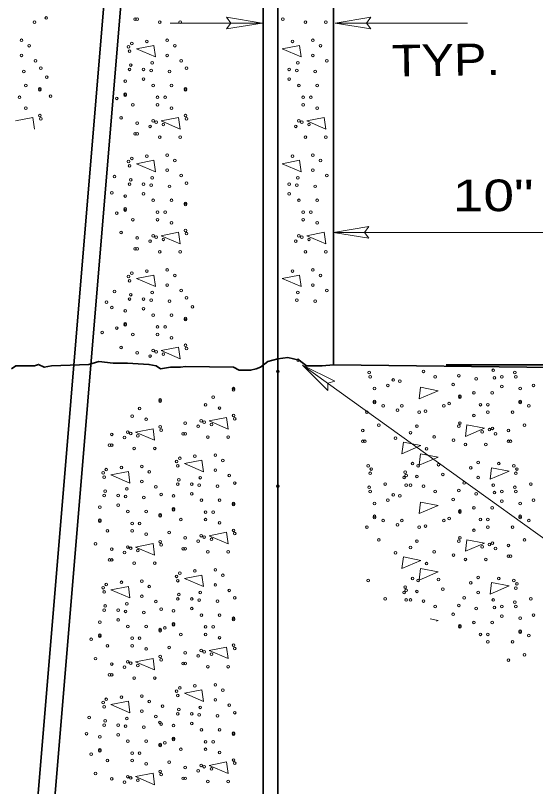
# Model space of a CAD drawing. Extents: x -16.43 to -9.36, y -8.57 to 1.26.
# Drawn here: x -13.889 to -12.904, y -2.302 to -0.843 of the extents above; entities that cross this region are included whole.
import ezdxf
from ezdxf.enums import TextEntityAlignment as Align

# ---------------------------------------------------------------- set-up
doc = ezdxf.new("R2010")
doc.units = 0
doc.header["$LTSCALE"] = 0.024
for name, color, linetype, lineweight in [('1', 7, 'Continuous', 35), ('10', 7, 'Continuous', 13), ('12', 7, 'Continuous', 53), ('6', 7, 'Continuous', 13)]:
    doc.layers.add(name, color=color, linetype=linetype, lineweight=lineweight)

msp = doc.modelspace()

# ---------------------------------------------------------------- linework, layer by layer
at = {"layer": '1'}
for p, q in [((-13.28633, 0.49133), (-13.28633, -1.504)), ((-13.392, 0.00867), (-13.392, -2.83033)), ((-13.66625, -0.552), (-13.85583, -2.82733)), ((-13.69975, -0.56375), (-13.88817, -2.82583)), ((-11.35133, -1.526), (-13.28633, -1.504)), ((-13.07283, -1.504), (-12.68283, -1.504))]:
    msp.add_line(p, q, dxfattribs=at)
for points in [[(-13.41917, 0.01217), (-13.41917, -2.83033), (-13.392, -2.83033)], [(-13.89617, -1.5115), (-13.888, -1.506), (-13.8745, -1.506), (-13.86083, -1.506), (-13.85267, -1.506), (-13.84467, -1.50333), (-13.83383, -1.50867), (-13.82017, -1.506), (-13.74967, -1.50333), (-13.73067, -1.49783), (-13.70367, -1.50067), (-13.6765, -1.50067), (-13.63583, -1.50333), (-13.62233, -1.506), (-13.61417, -1.5115), (-13.59517, -1.50867), (-13.57617, -1.50867), (-13.56633, -1.507)], [(-13.28633, -1.504), (-13.30767, -1.506), (-13.3375, -1.506), (-13.35117, -1.49517), (-13.37283, -1.48983), (-13.39183, -1.4925), (-13.41067, -1.49783), (-13.42433, -1.50867), (-13.4325, -1.5115), (-13.44333, -1.51417), (-13.465, -1.51417), (-13.47583, -1.50867), (-13.56633, -1.507)]]:
    msp.add_lwpolyline(points, dxfattribs=at)
msp.add_arc((-14.44102, -0.51249), 0.6001, 325.00798, 355.23636, dxfattribs=at)
at = {"layer": '10'}
for p, q in [((-13.48883, -0.84583), (-13.42167, -0.857)), ((-13.48883, -0.84583), (-13.4805, -0.857)), ((-13.21567, -0.84583), (-13.28283, -0.857)), ((-13.21567, -0.84583), (-13.224, -0.857)), ((-13.59533, -0.857), (-13.42167, -0.857)), ((-13.48883, -0.86817), (-13.42167, -0.857)), ((-13.48883, -0.86817), (-13.4805, -0.857)), ((-13.03283, -0.857), (-13.28283, -0.857)), ((-13.21567, -0.86817), (-13.28283, -0.857)), ((-13.21567, -0.86817), (-13.224, -0.857)), ((-13.21917, -1.24217), (-13.28633, -1.25333)), ((-13.21917, -1.2645), (-13.28633, -1.25333)), ((-13.21917, -1.24217), (-13.2275, -1.25333)), ((-13.21917, -1.2645), (-13.2275, -1.25333)), ((-13.297, -1.55283), (-13.345, -1.5045)), ((-13.284, -1.53467), (-13.345, -1.5045)), ((-13.284, -1.53467), (-13.29733, -1.53883)), ((-13.297, -1.55283), (-13.29733, -1.53883))]:
    msp.add_line(p, q, dxfattribs=at)
for points in [[(-13.28633, -1.25333), (-12.69033, -1.25333), (-11.3495, -1.25333)], [(-13.345, -1.5045), (-12.57717, -2.05633), (-12.43733, -2.05633)]]:
    msp.add_lwpolyline(points, dxfattribs=at)
at = {"layer": '6'}
for p, q in [((-13.08817, -1.98767), (-13.103, -1.98467)), ((-13.09117, -1.989), (-13.08817, -1.98767))]:
    msp.add_line(p, q, dxfattribs=at)
for points in [[(-13.6595, -0.906), (-13.6265, -0.8995), (-13.6235, -0.92133)], [(-13.38367, -0.906), (-13.35067, -0.8995), (-13.34783, -0.92133)], [(-13.61267, -1.04233), (-13.57967, -1.03583), (-13.57683, -1.05767)], [(-13.337, -1.04233), (-13.30383, -1.03583), (-13.301, -1.05767)], [(-13.6595, -1.12333), (-13.6265, -1.11683), (-13.6235, -1.13867)], [(-13.38367, -1.12333), (-13.35067, -1.11683), (-13.34783, -1.13867)], [(-13.61267, -1.25967), (-13.57967, -1.25317), (-13.57683, -1.27517)], [(-13.337, -1.25967), (-13.30383, -1.25317), (-13.301, -1.27517)], [(-13.6595, -1.34067), (-13.6265, -1.33417), (-13.6235, -1.356)], [(-13.38367, -1.34067), (-13.35067, -1.33417), (-13.34783, -1.356)], [(-13.61267, -1.477), (-13.57967, -1.4705), (-13.57683, -1.4925)], [(-13.08817, -1.553), (-13.12133, -1.5465), (-13.12417, -1.56833)], [(-13.52167, -1.61), (-13.48867, -1.60367), (-13.48567, -1.6255)], [(-13.00067, -1.62417), (-13.03367, -1.61767), (-13.0365, -1.63967)], [(-13.661, -1.6315), (-13.62783, -1.625), (-13.625, -1.64683)], [(-13.12067, -1.65683), (-13.15383, -1.65033), (-13.15667, -1.67217)], [(-13.08817, -1.67867), (-13.12133, -1.67217), (-13.12417, -1.694)], [(-13.5685, -1.691), (-13.53533, -1.6845), (-13.5325, -1.7065)], [(-13.70783, -1.7125), (-13.67467, -1.706), (-13.67183, -1.72783)], [(-12.95383, -1.70517), (-12.98683, -1.69867), (-12.98983, -1.7205)], [(-13.08817, -1.77033), (-13.12133, -1.76383), (-13.12417, -1.78567)], [(-13.52167, -1.8275), (-13.48867, -1.821), (-13.48567, -1.84283)], [(-13.00067, -1.8415), (-13.03367, -1.835), (-13.0365, -1.857)], [(-13.661, -1.84883), (-13.62783, -1.84233), (-13.625, -1.86417)], [(-13.12067, -1.87417), (-13.15383, -1.86767), (-13.15667, -1.8895)], [(-13.08817, -1.896), (-13.12133, -1.8895), (-13.12417, -1.9115)], [(-13.5685, -1.90833), (-13.53533, -1.90183), (-13.5325, -1.92383)], [(-13.70783, -1.92983), (-13.67467, -1.92333), (-13.67183, -1.94517)], [(-12.95383, -1.9225), (-12.98683, -1.916), (-12.98983, -1.938)], [(-13.52167, -2.04483), (-13.48867, -2.03833), (-13.48567, -2.06017)], [(-13.661, -2.06617), (-13.62783, -2.05967), (-13.625, -2.0815)], [(-13.5685, -2.12567), (-13.53533, -2.11933), (-13.5325, -2.14117)], [(-13.70783, -2.14717), (-13.67467, -2.14067), (-13.67183, -2.1625)], [(-13.52167, -2.26217), (-13.48867, -2.25567), (-13.48567, -2.2775)], [(-13.661, -2.2835), (-13.62783, -2.277), (-13.625, -2.299)]]:
    msp.add_lwpolyline(points, close=True, dxfattribs=at)
msp.add_lwpolyline([(-13.8885, -1.04233), (-13.8555, -1.03583), (-13.8525, -1.05767)], dxfattribs=at)
for centre in [(-13.83005, -0.8475), (-13.85245, -0.85562), (-13.66214, -0.84954), (-13.6581, -0.84954), (-13.61534, -0.85562), (-13.57665, -0.85562), (-13.3823, -0.84954), (-13.33953, -0.85562), (-13.30085, -0.85562), (-13.8769, -0.88975), (-13.63978, -0.89179), (-13.60109, -0.88975), (-13.36398, -0.89179), (-13.32529, -0.88975), (-13.86262, -0.89995), (-13.67439, -0.90199), (-13.66826, -0.89587), (-13.58681, -0.89995), (-13.31101, -0.89995), (-13.8769, -0.91827), (-13.67234, -0.91011), (-13.60109, -0.91827), (-13.32529, -0.91827), (-13.85041, -0.92844), (-13.6703, -0.9366), (-13.62958, -0.93252), (-13.57461, -0.92844), (-13.35377, -0.93252), (-13.29881, -0.92844), (-13.87282, -0.9488), (-13.84025, -0.94268), (-13.67234, -0.94472), (-13.64586, -0.94472), (-13.63162, -0.94676), (-13.59701, -0.9488), (-13.56445, -0.94268), (-13.37006, -0.94472), (-13.35581, -0.94676), (-13.32121, -0.9488), (-13.82933, -0.9596), (-13.64586, -0.96304), (-13.37006, -0.96304), (-13.86874, -0.97528), (-13.68047, -0.96712), (-13.62754, -0.97528), (-13.59293, -0.97528), (-13.35173, -0.97528), (-13.31713, -0.97528), (-13.84225, -0.98136), (-13.84225, -0.9834), (-13.68047, -0.99157), (-13.68047, -0.99361), (-13.56645, -0.98136), (-13.56645, -0.9834), (-13.88094, -0.99765), (-13.82193, -0.99565), (-13.69675, -0.99969), (-13.61942, -0.99765), (-13.60513, -0.99765), (-13.34361, -0.99765), (-13.32933, -0.99765), (-13.86874, -1.01801), (-13.66622, -1.01193), (-13.61942, -1.01193), (-13.59293, -1.01801), (-13.34361, -1.01193), (-13.31713, -1.01801), (-13.84225, -1.03229), (-13.84025, -1.03837), (-13.68863, -1.03633), (-13.56645, -1.03229), (-13.56445, -1.03837), (-13.6581, -1.04653), (-13.63366, -1.05262), (-13.62778, -1.04237), (-13.62214, -1.04481), (-13.60849, -1.04918), (-13.35785, -1.05262), (-13.35197, -1.04237), (-13.34633, -1.04481), (-13.33269, -1.04918), (-13.66214, -1.0669), (-13.6581, -1.0669), (-13.61534, -1.07298), (-13.57665, -1.07298), (-13.33953, -1.07298), (-13.30085, -1.07298), (-13.63978, -1.10915), (-13.60109, -1.1071), (-13.36398, -1.10915), (-13.32529, -1.1071), (-13.67439, -1.11935), (-13.66826, -1.11323), (-13.58681, -1.11731), (-13.31101, -1.11731), (-13.67234, -1.12747), (-13.60109, -1.13563), (-13.32529, -1.13563), (-13.70083, -1.14783), (-13.6703, -1.15395), (-13.62958, -1.14987), (-13.57461, -1.14579), (-13.35377, -1.14987), (-13.29881, -1.14579), (-13.67234, -1.16207), (-13.64586, -1.16207), (-13.63162, -1.16411), (-13.59701, -1.16615), (-13.56445, -1.16003), (-13.37006, -1.16207), (-13.35581, -1.16411), (-13.32121, -1.16615), (-13.70587, -1.17836), (-13.68047, -1.18448), (-13.64586, -1.1804), (-13.37006, -1.1804), (-13.62754, -1.19264), (-13.59293, -1.19264), (-13.56645, -1.19872), (-13.35173, -1.19264), (-13.31713, -1.19264), (-13.68047, -1.20892), (-13.68047, -1.21096), (-13.56645, -1.20076), (-13.69675, -1.21704), (-13.61942, -1.215), (-13.60513, -1.215), (-13.34361, -1.215), (-13.32933, -1.215), (-13.66622, -1.22928), (-13.61942, -1.22928), (-13.59293, -1.23537), (-13.34361, -1.22928), (-13.31713, -1.23537), (-13.68863, -1.25369), (-13.56645, -1.24965), (-13.56445, -1.25573), (-13.6581, -1.26389), (-13.63366, -1.26997), (-13.62778, -1.25973), (-13.62214, -1.26217), (-13.60849, -1.26653), (-13.35785, -1.26997), (-13.35197, -1.25973), (-13.34633, -1.26217), (-13.33269, -1.26653), (-13.66214, -1.28425), (-13.6581, -1.28425), (-13.61534, -1.29033), (-13.57665, -1.29033), (-13.33953, -1.29033), (-13.30085, -1.29033), (-13.66826, -1.33058), (-13.63978, -1.3265), (-13.60109, -1.32446), (-13.36398, -1.3265), (-13.32529, -1.32446), (-13.67439, -1.3367), (-13.67234, -1.34482), (-13.58681, -1.33466), (-13.31101, -1.33466), (-13.60109, -1.35298), (-13.32529, -1.35298), (-13.70083, -1.36519), (-13.6703, -1.37131), (-13.62958, -1.36723), (-13.57461, -1.36315), (-13.35377, -1.36723), (-13.29881, -1.36315), (-13.71603, -1.38555), (-13.67234, -1.37943), (-13.64586, -1.37943), (-13.63162, -1.38147), (-13.59701, -1.38351), (-13.56445, -1.37739), (-13.35581, -1.38147), (-13.32121, -1.38351), (-13.70587, -1.39571), (-13.68047, -1.40183), (-13.64586, -1.39775), (-13.55353, -1.39431), (-13.62754, -1.40999), (-13.59293, -1.40999), (-13.56645, -1.41607), (-13.56645, -1.41811), (-13.68047, -1.42628), (-13.68047, -1.42832), (-13.61942, -1.43236), (-13.60513, -1.43236), (-13.72419, -1.44256), (-13.69675, -1.4344), (-13.66622, -1.44664), (-13.61942, -1.44664), (-13.59293, -1.45272), (-13.68863, -1.47104), (-13.56645, -1.467), (-13.56445, -1.47308), (-13.6581, -1.48124), (-13.63366, -1.48733), (-13.62778, -1.47708), (-13.62214, -1.47952), (-13.60849, -1.48388), (-13.35348, -1.49549), (-13.39188, -1.51641), (-13.21881, -1.51845), (-13.11608, -1.51641), (-12.98374, -1.51437), (-12.94301, -1.51845), (-13.21677, -1.52657), (-13.17309, -1.53269), (-13.16085, -1.53473), (-13.09367, -1.52657), (-13.04887, -1.52453), (-13.0163, -1.53065), (-12.9817, -1.52861), (-12.96745, -1.52657), (-12.94097, -1.52657), (-13.47539, -1.5491), (-13.20865, -1.54898), (-13.18325, -1.54285), (-13.05979, -1.54145), (-12.96745, -1.54489), (-12.93285, -1.54898), (-12.90744, -1.54285), (-13.47539, -1.55114), (-13.04687, -1.56322), (-13.02038, -1.55714), (-12.98578, -1.55714), (-13.61466, -1.5705), (-13.61466, -1.57254), (-13.51408, -1.56538), (-13.20865, -1.57342), (-13.20865, -1.57546), (-13.06719, -1.5775), (-13.04687, -1.56526), (-12.93285, -1.57342), (-12.93285, -1.57546), (-13.65334, -1.58678), (-13.52836, -1.57966), (-13.50188, -1.58574), (-13.19237, -1.58154), (-13.16493, -1.5897), (-13.1568, -1.58154), (-13.112, -1.59174), (-13.07739, -1.58154), (-13.00818, -1.5795), (-12.9939, -1.5795), (-12.91657, -1.58154), (-13.66762, -1.60106), (-13.64114, -1.60714), (-13.47539, -1.60002), (-13.47339, -1.6061), (-13.2229, -1.59378), (-13.1242, -1.59378), (-13.02038, -1.59986), (-12.9939, -1.59378), (-12.94709, -1.59378), (-13.61466, -1.62143), (-13.56705, -1.61427), (-13.5426, -1.62035), (-13.53672, -1.61011), (-13.53108, -1.61255), (-13.51744, -1.61691), (-13.20049, -1.61819), (-13.12828, -1.62023), (-13.04887, -1.62023), (-13.04687, -1.61415), (-12.92469, -1.61819), (-13.70631, -1.63567), (-13.67599, -1.63151), (-13.67034, -1.63395), (-13.61266, -1.62751), (-13.57109, -1.63463), (-13.56705, -1.63463), (-13.23102, -1.62839), (-13.14048, -1.63247), (-13.00482, -1.63103), (-12.99118, -1.62667), (-12.98554, -1.62423), (-12.97966, -1.63447), (-12.95521, -1.62839), (-13.68187, -1.64175), (-13.6567, -1.63831), (-13.52428, -1.64071), (-13.4856, -1.64071), (-13.23102, -1.64875), (-13.22698, -1.64875), (-13.16901, -1.64263), (-13.09571, -1.64059), (-13.05907, -1.64671), (-12.95521, -1.64875), (-12.95117, -1.64875), (-13.71035, -1.65603), (-13.70631, -1.65603), (-13.66354, -1.66211), (-13.62486, -1.66211), (-13.10996, -1.66299), (-13.03667, -1.65483), (-12.99798, -1.65483), (-13.57721, -1.68096), (-13.54873, -1.67688), (-13.51004, -1.67484), (-13.58333, -1.68708), (-13.58129, -1.6952), (-13.49576, -1.68504), (-13.22085, -1.69508), (-13.13644, -1.691), (-13.12624, -1.69508), (-13.08755, -1.69304), (-13.01222, -1.68896), (-12.97354, -1.691), (-12.94505, -1.69508), (-13.72259, -1.70848), (-13.71647, -1.70236), (-13.68799, -1.69828), (-13.6493, -1.69624), (-13.63502, -1.70644), (-13.51004, -1.70336), (-13.21677, -1.70932), (-13.21473, -1.7012), (-13.15068, -1.70728), (-13.0265, -1.69916), (-12.94097, -1.70932), (-12.93893, -1.7012), (-13.72055, -1.7166), (-13.6493, -1.72476), (-13.57925, -1.72168), (-13.53852, -1.7176), (-13.48355, -1.71352), (-13.15272, -1.71748), (-13.14864, -1.7134), (-13.12828, -1.71544), (-13.07943, -1.71136), (-13.01222, -1.71748), (-13.67779, -1.73901), (-13.62282, -1.73493), (-13.58129, -1.7298), (-13.55481, -1.7298), (-13.54056, -1.73184), (-13.50596, -1.73388), (-13.47339, -1.72776), (-13.39188, -1.73376), (-13.21881, -1.73581), (-13.18829, -1.72968), (-13.14864, -1.73172), (-13.14048, -1.73172), (-13.11608, -1.73376), (-13.03871, -1.72764), (-12.98374, -1.73172), (-12.94301, -1.73581), (-12.91249, -1.72968), (-13.72055, -1.75121), (-13.71851, -1.74309), (-13.69407, -1.75121), (-13.67983, -1.75325), (-13.61266, -1.74917), (-13.58941, -1.75221), (-13.55481, -1.74813), (-13.21677, -1.74393), (-13.17309, -1.75005), (-13.16085, -1.75209), (-13.09367, -1.74393), (-13.04887, -1.74189), (-13.0163, -1.74801), (-12.9817, -1.74597), (-12.96745, -1.74393), (-12.94097, -1.74393), (-13.64522, -1.75529), (-13.53648, -1.76037), (-13.50188, -1.76037), (-13.47539, -1.76645), (-13.47539, -1.76849), (-13.20865, -1.76633), (-13.18325, -1.76021), (-13.05979, -1.75881), (-12.96745, -1.76225), (-12.93285, -1.76633), (-12.90744, -1.76021), (-13.72867, -1.77361), (-13.69407, -1.76953), (-13.67575, -1.78177), (-13.64114, -1.78177), (-13.58941, -1.77665), (-13.58941, -1.77869), (-13.52836, -1.78273), (-13.51408, -1.78273), (-13.04687, -1.78057), (-13.04687, -1.78261), (-13.02038, -1.77449), (-12.98578, -1.77449), (-13.61466, -1.78785), (-13.61466, -1.78989), (-13.57517, -1.79702), (-13.52836, -1.79702), (-13.20865, -1.79077), (-13.20865, -1.79281), (-13.06719, -1.79485), (-13.00818, -1.79686), (-12.9939, -1.79686), (-12.93285, -1.79077), (-12.93285, -1.79281), (-13.72867, -1.79806), (-13.72867, -1.8001), (-13.66762, -1.80414), (-13.65334, -1.80414), (-13.50188, -1.8031), (-13.2229, -1.81114), (-13.19237, -1.7989), (-13.16493, -1.80706), (-13.1568, -1.7989), (-13.1242, -1.81114), (-13.112, -1.8091), (-13.07739, -1.7989), (-12.9939, -1.81114), (-12.94709, -1.81114), (-12.91657, -1.7989), (-13.71443, -1.81842), (-13.66762, -1.81842), (-13.64114, -1.8245), (-13.59757, -1.82142), (-13.47539, -1.81738), (-13.47339, -1.82346), (-13.02038, -1.81722), (-13.61466, -1.83878), (-13.56705, -1.83162), (-13.5426, -1.8377), (-13.53672, -1.82746), (-13.53108, -1.8299), (-13.51744, -1.83426), (-13.20049, -1.83554), (-13.12828, -1.83758), (-13.04887, -1.83758), (-13.04687, -1.8315), (-12.98554, -1.84158), (-12.92469, -1.83554), (-13.73684, -1.84282), (-13.70631, -1.85302), (-13.67599, -1.84886), (-13.67034, -1.8513), (-13.6567, -1.85566), (-13.61266, -1.84486), (-13.57109, -1.85198), (-13.56705, -1.85198), (-13.14048, -1.84982), (-13.00482, -1.84838), (-12.99118, -1.84402), (-12.97966, -1.85182), (-12.95521, -1.84574), (-13.68187, -1.8591), (-13.52428, -1.85806), (-13.4856, -1.85806), (-13.16901, -1.85999), (-13.09571, -1.85794), (-13.05907, -1.86407), (-12.95521, -1.86611), (-12.95117, -1.86611), (-13.71035, -1.87339), (-13.70631, -1.87339), (-13.66354, -1.87947), (-13.62486, -1.87947), (-13.10996, -1.88035), (-13.03667, -1.87219), (-12.99798, -1.87219), (-13.57721, -1.89831), (-13.54873, -1.89423), (-13.51004, -1.89219), (-13.6493, -1.91359), (-13.58333, -1.90443), (-13.58129, -1.91255), (-13.49576, -1.90239), (-13.22085, -1.91243), (-13.13644, -1.90835), (-13.12624, -1.91243), (-13.08755, -1.91039), (-13.01222, -1.90631), (-12.97354, -1.90835), (-12.94505, -1.91243), (-13.72259, -1.92584), (-13.71647, -1.91971), (-13.68799, -1.91563), (-13.63502, -1.9238), (-13.51004, -1.92071), (-13.15068, -1.92464), (-13.07943, -1.92872), (-13.0265, -1.91651), (-12.94097, -1.92668), (-12.93893, -1.91855), (-13.72055, -1.93396), (-13.6493, -1.94212), (-13.57925, -1.93904), (-13.53852, -1.93496), (-13.48355, -1.93088), (-13.15272, -1.93484), (-13.14864, -1.93076), (-13.12828, -1.9328), (-13.01222, -1.93484), (-13.67779, -1.95636), (-13.62282, -1.95228), (-13.58129, -1.94716), (-13.55481, -1.94716), (-13.54056, -1.9492), (-13.50596, -1.95124), (-13.47339, -1.94512), (-13.18829, -1.94704), (-13.14864, -1.94908), (-13.14048, -1.94908), (-13.11608, -1.95112), (-13.03871, -1.945), (-12.98374, -1.94908), (-12.94301, -1.95316), (-12.91249, -1.94704), (-13.72055, -1.96856), (-13.71851, -1.96044), (-13.69407, -1.96856), (-13.67983, -1.9706), (-13.64522, -1.97264), (-13.61266, -1.96652), (-13.58941, -1.96956), (-13.55481, -1.96548), (-13.09367, -1.96128), (-13.04887, -1.95924), (-13.0163, -1.96536), (-12.9817, -1.96332), (-12.96745, -1.96128), (-12.94097, -1.96128), (-13.69407, -1.98689), (-13.53648, -1.97772), (-13.50188, -1.97772), (-13.47539, -1.9838), (-13.47539, -1.98585), (-13.05979, -1.97616), (-12.96745, -1.9796), (-12.93285, -1.98368), (-12.90744, -1.97756), (-13.72867, -1.99097), (-13.67575, -1.99913), (-13.64114, -1.99913), (-13.60569, -2.00213), (-13.58941, -1.99401), (-13.58941, -1.99605), (-13.52836, -2.00009), (-13.51408, -2.00009), (-13.04687, -1.99793), (-13.04687, -1.99997), (-13.02038, -1.99185), (-12.98578, -1.99185), (-13.72867, -2.01541), (-13.61466, -2.00521), (-13.61466, -2.00725), (-13.57517, -2.01437), (-13.52836, -2.01437), (-13.00818, -2.01421), (-12.9939, -2.01421), (-12.93285, -2.00813), (-12.93285, -2.01017), (-12.91657, -2.01625), (-13.74496, -2.02353), (-13.72867, -2.01745), (-13.66762, -2.02149), (-13.65334, -2.02149), (-13.50188, -2.02045), (-12.9939, -2.02849), (-12.94709, -2.02849), (-13.71443, -2.03577), (-13.66762, -2.03577), (-13.64114, -2.04185), (-13.59757, -2.03877), (-13.53672, -2.04481), (-13.47539, -2.03473), (-13.47339, -2.04081), (-13.73684, -2.06018), (-13.61466, -2.05614), (-13.56705, -2.04898), (-13.5426, -2.05506), (-13.53108, -2.04726), (-13.51744, -2.05162), (-12.92469, -2.0529), (-13.70631, -2.07038), (-13.67599, -2.06622), (-13.67034, -2.06866), (-13.6567, -2.07302), (-13.61266, -2.06222), (-13.57109, -2.06934), (-13.56705, -2.06934), (-12.95521, -2.0631), (-13.68187, -2.07646), (-13.52428, -2.07542), (-13.4856, -2.07542), (-13.71035, -2.09074), (-13.70631, -2.09074), (-13.66354, -2.09682), (-13.62486, -2.09682), (-13.57721, -2.11567), (-13.54873, -2.11159), (-13.51004, -2.10955), (-13.68799, -2.13299), (-13.6493, -2.13095), (-13.58333, -2.12179), (-13.58129, -2.12991), (-13.49576, -2.11975), (-13.72259, -2.14319), (-13.71647, -2.13707), (-13.63502, -2.14115), (-13.51004, -2.13807), (-13.72055, -2.15131), (-13.6493, -2.15947), (-13.60977, -2.15027), (-13.57925, -2.15639), (-13.53852, -2.15231), (-13.48355, -2.14823), (-13.47339, -2.16247), (-13.74904, -2.17168), (-13.67779, -2.17372), (-13.62282, -2.16963), (-13.58129, -2.16451), (-13.55481, -2.16451), (-13.54056, -2.16655), (-13.50596, -2.16859), (-13.72055, -2.18592), (-13.71851, -2.1778), (-13.69407, -2.18592), (-13.67983, -2.18796), (-13.64522, -2.19), (-13.61482, -2.1808), (-13.61266, -2.18388), (-13.58941, -2.18692), (-13.55481, -2.18284), (-13.75408, -2.2022), (-13.69407, -2.20424), (-13.53648, -2.19508), (-13.50188, -2.19508), (-13.47539, -2.20116), (-13.47539, -2.2032), (-13.72867, -2.20832), (-13.67575, -2.21648), (-13.64114, -2.21648), (-13.60569, -2.21948), (-13.58941, -2.21136), (-13.58941, -2.2134), (-13.52836, -2.21744), (-13.51408, -2.21744), (-13.72867, -2.23276), (-13.72867, -2.23481), (-13.61466, -2.22256), (-13.61466, -2.2246), (-13.57517, -2.23172), (-13.52836, -2.23172), (-13.74496, -2.24089), (-13.66762, -2.23885), (-13.65334, -2.23885), (-13.50188, -2.23781), (-13.71443, -2.25313), (-13.66762, -2.25313), (-13.64114, -2.25921), (-13.59757, -2.25613), (-13.53672, -2.26217), (-13.53108, -2.26461), (-13.47539, -2.25209), (-13.47339, -2.25817), (-13.73684, -2.27753), (-13.61466, -2.27349), (-13.56705, -2.26633), (-13.5426, -2.27241), (-13.51744, -2.26897), (-13.70631, -2.28773), (-13.68187, -2.29381), (-13.67599, -2.28357), (-13.67034, -2.28601), (-13.6567, -2.29037), (-13.61266, -2.27957), (-13.57109, -2.28669), (-13.56705, -2.28669), (-13.52428, -2.29277), (-13.4856, -2.29277)]:
    msp.add_circle(centre, 0.00252, dxfattribs=at)

# ---------------------------------------------------------------- texts
at = {"layer": '12', "width": 1.15}
msp.add_text('TYP.', height=0.06001, rotation=1, dxfattribs=at).set_placement((-13.07307, -0.95689), align=Align.CENTER)
at = {"layer": '12', "width": 1.3}
msp.add_text('10"', height=0.06001, dxfattribs=at).set_placement((-12.984, -1.21325), align=Align.CENTER)

doc.saveas('drawing.dxf')
